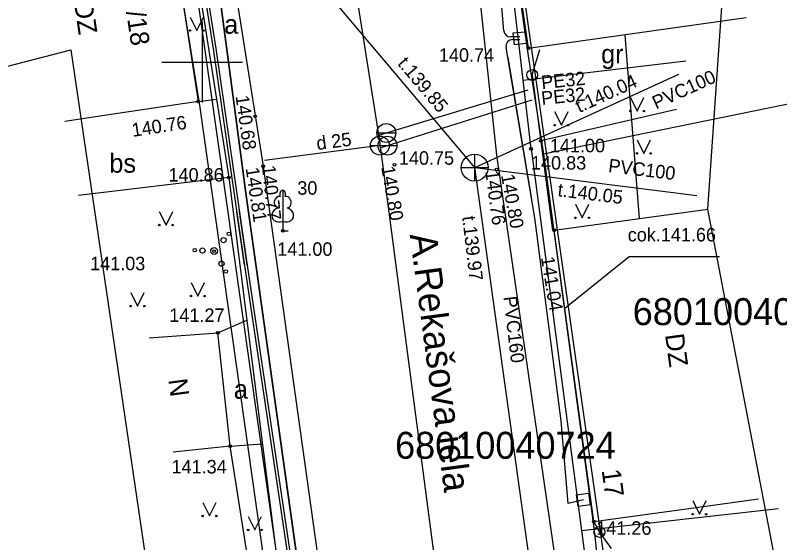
# Model space of a CAD drawing. Extents: x 728710 to 728960, y 272811 to 273475.
# Drawn here: x 728793.07 to 728821.41, y 273182.19 to 273201.73 of the extents above; entities that cross this region are included whole.
import ezdxf

# ---------------------------------------------------------------- set-up
doc = ezdxf.new("R2010")
doc.units = 0
for name, color, linetype in [('GEOD_ELEM_####_TKST_#', 7, 'Continuous'), ('Level 10', 7, 'Continuous'), ('Level 15', 7, 'Continuous'), ('Level 17', 7, 'Continuous'), ('Level 23', 7, 'Continuous'), ('Level 28', 7, 'Continuous'), ('Level 29', 7, 'Continuous'), ('Level 3', 7, 'Continuous'), ('Level 36', 7, 'Continuous'), ('Level 39', 7, 'Continuous'), ('Level 4', 7, 'Continuous'), ('Level 43', 7, 'Continuous'), ('Level 48', 7, 'Continuous'), ('Level 50', 7, 'Continuous'), ('Level 54', 7, 'Continuous'), ('Level 55', 7, 'Continuous'), ('Level 56', 7, 'Continuous'), ('Level 57', 7, 'Continuous'), ('Level 58', 7, 'Continuous'), ('Level 59', 7, 'Continuous'), ('Level 60', 7, 'Continuous'), ('Level 62', 7, 'Continuous'), ('Level 9', 7, 'Continuous'), ('RAMI_UZMR_####_####_#', 7, 'Continuous'), ('RELJ_ELEM_####_####_#', 7, 'Continuous'), ('RELJ_NOGA_####_####_#', 7, 'Continuous'), ('ROBZ_ELEM_####_####_#', 7, 'Continuous'), ('ROBZ_KADS_####_TKST_#', 7, 'Continuous'), ('ROBZ_UZMR_####_####_#', 7, 'Continuous'), ('TERT_ELEM_####_####_#', 7, 'Continuous'), ('TERT_KONT_####_####_#', 7, 'Continuous')]:
    doc.layers.add(name, color=color, linetype=linetype)

msp = doc.modelspace()

# ---------------------------------------------------------------- linework, layer by layer
at = {"layer": 'GEOD_ELEM_####_TKST_#'}
msp.add_lwpolyline([(728806.989, 273165.064), (728806.014, 273164.984), (728805.919, 273164.996), (728805.829, 273165.094), (728801.63, 273195.055), (728800.391, 273204.396), (728800.452, 273204.629), (728801.02, 273204.847)], dxfattribs=at)
at = {"layer": 'Level 10'}
for p, q in [((728800, 273201.5), (728800, 273200)), ((728798.5, 273200), (728800, 273200)), ((728800, 273200), (728800, 273198.5)), ((728800, 273200), (728801.5, 273200))]:
    msp.add_line(p, q, dxfattribs=at)
at = {"layer": 'Level 15'}
for points in [[(728812.027, 273200.685), (728811.582, 273200.637), (728811.535, 273201.075), (728811.98, 273201.123)], [(728814.389, 273183.587), (728813.947, 273183.524), (728813.885, 273183.959), (728814.327, 273184.022)]]:
    msp.add_lwpolyline(points, close=True, dxfattribs=at)
at = {"layer": 'Level 17'}
for p, q in [((728812.076, 273198.955), (728806.537, 273197.282)), ((728806.603, 273196.817), (728812.231, 273198.595)), ((728806.592, 273196.904), (728802.311, 273196.347))]:
    msp.add_line(p, q, dxfattribs=at)
for points in [[(728804.594, 273209.577), (728806.57, 273197.07)], [(728806.57, 273197.07), (728809.225, 273176.951)]]:
    msp.add_lwpolyline(points, dxfattribs=at)
at = {"layer": 'Level 23'}
for points in [[(728810.106, 273196.087), (728797.551, 273210.954)], [(728810.106, 273196.087), (728817.675, 273199.548)], [(728810.106, 273196.087), (728818.347, 273195.048)], [(728812.664, 273177.733), (728810.106, 273196.087)]]:
    msp.add_lwpolyline(points, dxfattribs=at)
at = {"layer": 'Level 28'}
for points in [[(728812.239, 273199.508), (728812.986, 273193.756)], [(728817.584, 273198.236), (728812.554, 273197.083)], [(728802.126, 273178.859), (728801.035, 273185.766)], [(728814.73, 273182.588), (728814.526, 273182.977)]]:
    msp.add_lwpolyline(points, dxfattribs=at)
at = {"layer": 'Level 29'}
for p, q in [((728810.106, 273195.587), (728810.106, 273196.587)), ((728809.606, 273196.087), (728810.606, 273196.087))]:
    msp.add_line(p, q, dxfattribs=at)
msp.add_circle((728810.106, 273196.087), 0.5, dxfattribs=at)
at = {"layer": 'Level 3'}
for p, q in [((728812.098, 273200.51), (728811.193, 273206.959)), ((728798.835, 273205.109), (728799.854, 273198.536)), ((728812.098, 273200.51), (728820.175, 273201.643)), ((728799.854, 273198.536), (728796.29, 273198)), ((728796.29, 273198), (728794.906, 273197.794)), ((728813.048, 273193.765), (728818.749, 273194.545)), ((728814.526, 273182.977), (728813.048, 273193.765)), ((728798.031, 273189.775), (728800.585, 273189.966)), ((728801.035, 273185.766), (728800.585, 273189.966)), ((728801.035, 273185.766), (728798.927, 273185.54)), ((728818.312, 273183.496), (728820.623, 273183.812)), ((728814.526, 273182.977), (728818.312, 273183.496))]:
    msp.add_line(p, q, dxfattribs=at)
at = {"layer": 'Level 36'}
msp.add_line((728801.67, 273192.488), (728801.383, 273194.463), dxfattribs=at)
for points in [[(728811.335, 273200.162), (728812.202, 273194.989)], [(728801.571, 273192.474), (728801.284, 273194.449)]]:
    msp.add_lwpolyline(points, dxfattribs=at)
at = {"layer": 'Level 39'}
for p, q in [((728806.477, 273197.37), (728807.179, 273197.37)), ((728806.827, 273197.37), (728806.827, 273197.371)), ((728806.241, 273196.904), (728806.943, 273196.904)), ((728806.518, 273196.901), (728807.22, 273196.901)), ((728806.591, 273196.904), (728806.591, 273196.905)), ((728806.868, 273196.901), (728806.868, 273196.902))]:
    msp.add_line(p, q, dxfattribs=at)
for centre in [(728806.828, 273197.37), (728806.592, 273196.904), (728806.869, 273196.901)]:
    msp.add_circle(centre, 0.351, dxfattribs=at)
at = {"layer": 'Level 4'}
for p, q in [((728799.854, 273198.536), (728800.536, 273198.621)), ((728812.193, 273196.782), (728814.243, 273181.329)), ((728800.585, 273189.966), (728801.656, 273190.44)), ((728801.035, 273185.766), (728802.232, 273185.847))]:
    msp.add_line(p, q, dxfattribs=at)
for points in [[(728809.644, 273208.462), (728810.915, 273196.542), (728813.126, 273181.312)], [(728812.193, 273196.782), (728810.951, 273207.517)], [(728800.722, 273205.914), (728802.266, 273196.137), (728804.601, 273179.443)], [(728799.446, 273205.539), (728800.992, 273195.724), (728803.086, 273179.05)], [(728811.899, 273199.324), (728817.929, 273200.04)], [(728800.992, 273195.724), (728795.414, 273195.058)], [(728814.069, 273182.641), (728821.369, 273183.451)]]:
    msp.add_lwpolyline(points, dxfattribs=at)
at = {"layer": 'Level 43'}
for p, q in [((728812.237, 273199.519), (728812.521, 273200.467)), ((728815.182, 273181.974), (728814.73, 273182.588))]:
    msp.add_line(p, q, dxfattribs=at)
for centre in [(728812.237, 273199.519), (728814.73, 273182.588)]:
    msp.add_circle(centre, 0.202, dxfattribs=at)
at = {"layer": 'Level 48'}
for centre in [(728812.098, 273200.51), (728799.854, 273198.536), (728801.967, 273197.986), (728812.554, 273197.083), (728812.193, 273196.782), (728802.266, 273196.137), (728807.13, 273196.187), (728810.915, 273196.013), (728800.992, 273195.724), (728813.048, 273193.765), (728802.987, 273193.748), (728800.445, 273192.993), (728800.585, 273189.966), (728801.035, 273185.766), (728814.526, 273182.977)]:
    msp.add_circle(centre, 0.05, dxfattribs=at)
at = {"layer": 'Level 9'}
for points in [[(728813.444, 273190.875), (728815.827, 273192.797), (728816.891, 273192.797)], [(728816.891, 273192.797), (728819.185, 273192.797)]]:
    msp.add_lwpolyline(points, dxfattribs=at)
at = {"layer": 'RAMI_UZMR_####_####_#'}
for points in [[(728838.026, 273158.297), (728833.202, 273166.507), (728833.235, 273168.344), (728821.579, 273179.812), (728818.749, 273194.545), (728819.331, 273202.951), (728829.731, 273204.761), (728829.577, 273209.987), (728827.575, 273221.822), (728826.396, 273224.831), (728813.325, 273229.618), (728810.773, 273260.978), (728802.611, 273315.901)], [(728776.746, 273299.712), (728774.767, 273288.109), (728769.195, 273286.654), (728770.672, 273271.11), (728776.42, 273245.146), (728778.568, 273229.68), (728773.046, 273228.469), (728773.87, 273214.498), (728774.426, 273201.627), (728776.99, 273195.753), (728795.127, 273200.451), (728799.264, 273172.386), (728794.758, 273166.22), (728789.327, 273163.194), (728788.892, 273161.497), (728790.999, 273149.932)], [(728815.671, 273201.011), (728816.208, 273194.198)]]:
    msp.add_lwpolyline(points, dxfattribs=at)
at = {"layer": 'RELJ_ELEM_####_####_#'}
msp.add_lwpolyline([(728801.02, 273204.847), (728800.592, 273204.683), (728800.452, 273204.629), (728800.391, 273204.396), (728801.63, 273195.055), (728805.803, 273165.389), (728805.847, 273165.074), (728805.919, 273164.996), (728806.11, 273164.973), (728807.003, 273165.091)], dxfattribs=at)
at = {"layer": 'ROBZ_ELEM_####_####_#'}
for points in [[(728811.24, 273207.332), (728816.642, 273169.324)], [(728799.369, 273205.575), (728804.76, 273167.644)]]:
    msp.add_lwpolyline(points, dxfattribs=at)
at = {"layer": 'ROBZ_UZMR_####_####_#'}
for p, q in [((728811.158, 273206.807), (728812.087, 273200.226)), ((728798.857, 273204.918), (728799.91, 273198.314)), ((728812.087, 273200.226), (728812.658, 273196.583)), ((728825.793, 273199.272), (728812.658, 273196.583)), ((728799.91, 273198.314), (728804.732, 273164.296)), ((728812.658, 273196.583), (728814.525, 273182.736)), ((728814.525, 273182.736), (728814.987, 273178.617))]:
    msp.add_line(p, q, dxfattribs=at)
at = {"layer": 'TERT_ELEM_####_####_#'}
msp.add_line((728811.518, 273200.83), (728811.781, 273200.83), dxfattribs=at)
for points in [[(728811.191, 273201.159), (728810.98, 273203.671), (728810.518, 273206.443)], [(728799.868, 273203.925), (728800.411, 273200.491), (728801.537, 273192.703), (728803.228, 273181.337), (728804.575, 273171.658), (728805.512, 273165.011)], [(728799.956, 273204.011), (728800.509, 273200.505), (728801.635, 273192.717), (728803.326, 273181.351), (728804.675, 273171.672), (728805.612, 273165.025)], [(728811.781, 273200.93), (728811.443, 273200.93), (728811.443, 273200.93)], [(728814.137, 273183.773), (728813.566, 273183.639), (728813.309, 273186.699), (728812.33, 273194.228), (728811.272, 273200.539)]]:
    msp.add_lwpolyline(points, dxfattribs=at)
for centre, start, end in [((728811.44, 273201.18), 184.8095, 270.5026), ((728811.518, 273200.58), 90.0002, 189.5182)]:
    msp.add_arc(centre, 0.25, start, end, dxfattribs=at)
at = {"layer": 'TERT_KONT_####_####_#'}
for p, q in [((728799.554, 273201.667), (728799.804, 273201.167)), ((728799.804, 273201.167), (728800.054, 273201.667)), ((728815.879, 273198.683), (728816.129, 273198.183)), ((728816.129, 273198.183), (728816.379, 273198.683)), ((728813.07, 273198.16), (728813.32, 273197.66)), ((728813.32, 273197.66), (728813.57, 273198.16)), ((728816.124, 273197.114), (728816.374, 273196.614)), ((728816.374, 273196.614), (728816.624, 273197.114)), ((728813.838, 273194.727), (728814.088, 273194.227)), ((728814.088, 273194.227), (728814.338, 273194.727)), ((728798.411, 273194.459), (728798.661, 273193.959)), ((728798.661, 273193.959), (728798.911, 273194.459)), ((728802.987, 273194.095), (728802.987, 273193.748)), ((728802.987, 273193.748), (728803.187, 273193.748)), ((728799.592, 273191.827), (728799.842, 273191.327)), ((728799.842, 273191.327), (728800.092, 273191.827)), ((728797.353, 273191.455), (728797.603, 273190.955)), ((728797.603, 273190.955), (728797.853, 273191.455)), ((728800.021, 273183.678), (728800.271, 273183.178)), ((728800.271, 273183.178), (728800.521, 273183.678)), ((728818.187, 273183.746), (728818.437, 273183.246)), ((728818.437, 273183.246), (728818.687, 273183.746)), ((728801.707, 273183.164), (728801.957, 273182.664)), ((728801.957, 273182.664), (728802.207, 273183.164))]:
    msp.add_line(p, q, dxfattribs=at)
for points in [[(728802.987, 273195.248), (728802.987, 273194.095)], [(728803.077, 273195.016), (728803.076, 273195.017)]]:
    msp.add_lwpolyline(points, dxfattribs=at)
for centre, radius in [((728799.554, 273201.167), 0.028), ((728800.054, 273201.167), 0.0263), ((728815.879, 273198.182), 0.028), ((728816.379, 273198.182), 0.0263), ((728813.07, 273197.659), 0.028), ((728813.57, 273197.659), 0.0263), ((728816.124, 273196.613), 0.028), ((728816.624, 273196.613), 0.0263), ((728813.837, 273194.227), 0.028), ((728814.337, 273194.227), 0.0263), ((728798.411, 273193.958), 0.028), ((728798.911, 273193.958), 0.0263), ((728800.989, 273193.632), 0.064), ((728800.793, 273193.401), 0.096), ((728799.727, 273193.027), 0.064), ((728800.011, 273193.014), 0.096), ((728800.445, 273192.993), 0.128), ((728800.721, 273192.526), 0.096), ((728800.879, 273192.237), 0.064), ((728799.592, 273191.327), 0.028), ((728800.092, 273191.327), 0.0263), ((728797.353, 273190.955), 0.028), ((728797.853, 273190.955), 0.0263), ((728800.021, 273183.178), 0.028), ((728800.521, 273183.178), 0.0263), ((728818.187, 273183.245), 0.028), ((728818.687, 273183.245), 0.0263), ((728801.707, 273182.663), 0.028), ((728802.207, 273182.663), 0.0263)]:
    msp.add_circle(centre, radius, dxfattribs=at)
for centre, major_axis, ratio, start_param, end_param in [((728802.987, 273195.098), (0, -0.15), 0.707107, 3.14537, 5.287485), ((728802.987, 273195.098), (0, -0.15), 0.707107, 0.995701, 3.137816), ((728802.859, 273194.803), (-0.039, -0.212), 0.861323, 3.141593, 6.283185), ((728803.115, 273194.803), (0.039, -0.212), 0.861323, 0, 3.141593), ((728802.897, 273194.341), (0.307, 0.095), 0.814445, 1.570796, 4.752015), ((728803.077, 273194.341), (-0.307, 0.095), 0.814445, 1.531171, 4.712389)]:
    msp.add_ellipse(centre, major_axis=major_axis, ratio=ratio, start_param=start_param, end_param=end_param, dxfattribs=at)

# ---------------------------------------------------------------- texts
at = {"layer": 'Level 50'}
msp.add_text('cok.141.66', height=0.5, dxfattribs=at).set_placement((728815.779, 273193.352))
at = {"layer": 'Level 54'}
msp.add_text('A.Rekašova iela', height=1, rotation=277.641, dxfattribs=at).set_placement((728807.694, 273193.602))
at = {"layer": 'Level 55'}
for s, rotation, p in [('PE32', 5.861, (728812.6, 273198.991)), ('PE32', 5.861, (728812.6, 273198.406)), ('d 25', 7.4113, (728804.271, 273196.734))]:
    msp.add_text(s, height=0.5, rotation=rotation, dxfattribs=at).set_placement(p)
at = {"layer": 'Level 56'}
msp.add_text(' 140.75', height=0.5, dxfattribs=at).set_placement((728807.109, 273196.194))
at = {"layer": 'Level 57'}
for s, p in [(' 140.74', (728808.594, 273200.009)), (' 141.00', (728812.707, 273196.654)), ('140.83', (728812.193, 273196.013)), ('140.86', (728798.754, 273195.569)), (' 141.00', (728802.601, 273192.819)), (' 141.03', (728795.661, 273192.284)), (' 141.27', (728798.598, 273190.368)), (' 141.34', (728798.68, 273184.754)), (' 141.26', (728814.426, 273182.482))]:
    msp.add_text(s, height=0.5, dxfattribs=at).set_placement(p)
for s, rotation, p in [(' 140.68', 278.0797, (728801.211, 273198.918)), (' 140.76', 8.4946, (728797.246, 273197.198)), ('140.77', 276.3351, (728802.215, 273196.149)), ('140.80', 279.7547, (728806.637, 273196.102)), ('140.81', 278.584, (728801.611, 273196.062)), ('140.76', 277.6607, (728810.494, 273195.954)), ('140.80', 280.257, (728811.079, 273195.809)), (' 141.04', 279.2234, (728812.53, 273192.939))]:
    msp.add_text(s, height=0.5, rotation=rotation, dxfattribs=at).set_placement(p)
at = {"layer": 'Level 58'}
for s, p in [('a', (728800.817, 273201.048)), ('gr', (728814.793, 273199.948)), ('bs', (728796.561, 273195.899)), ('a', (728801.174, 273187.524))]:
    msp.add_text(s, height=0.7, dxfattribs=at).set_placement(p)
at = {"layer": 'Level 59'}
for s, rotation, p in [('DZ', 278.489, (728795.245, 273202.211)), ('DZ', 277.801, (728817.16, 273189.894)), ('N', 277.723, (728798.746, 273188.228))]:
    msp.add_text(s, height=0.7, rotation=rotation, dxfattribs=at).set_placement(p)
at = {"layer": 'Level 60'}
for s, rotation, p in [('t.139.85', 310.179, (728807.219, 273199.928)), ('t.140.04', 24.572, (728813.982, 273198.104)), ('PVC100', 24.572, (728816.83, 273198.236)), ('PVC100', 353.049, (728815.041, 273195.923)), ('t.140.05', 353.049, (728813.164, 273195.028)), ('t.139.97', 276.687, (728809.639, 273194.269)), ('PVC160', 276.687, (728811.17, 273191.298))]:
    msp.add_text(s, height=0.5, rotation=rotation, dxfattribs=at).set_placement(p)
at = {"layer": 'Level 62'}
for s, rotation, p in [('7/18', 278.489, (728797.106, 273202.367)), ('17', 277.801, (728814.812, 273184.872))]:
    msp.add_text(s, height=0.7, rotation=rotation, dxfattribs=at).set_placement(p)
at = {"layer": 'RELJ_NOGA_####_####_#'}
msp.add_text('30', height=0.5, dxfattribs=at).set_placement((728803.529, 273195.082))
at = {"layer": 'ROBZ_KADS_####_TKST_#'}
for s, p in [('68010040327', (728815.964, 273190.25)), ('68010040724', (728807.153, 273185.297))]:
    msp.add_text(s, height=1, dxfattribs=at).set_placement(p)

doc.saveas('drawing.dxf')
